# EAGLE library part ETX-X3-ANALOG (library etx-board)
VGA, LCD, Video, COM1, COM2, LPT/Floppy, IrDA, Mouse, Keyboard PARALLEL INTERFACE PINOUT, FLOPPY SUPPORT MODE PINOUT ETX Board Connector 100 Pos. Source: www.kontron.com/techlib/whitepapers/etx_spec.pdf
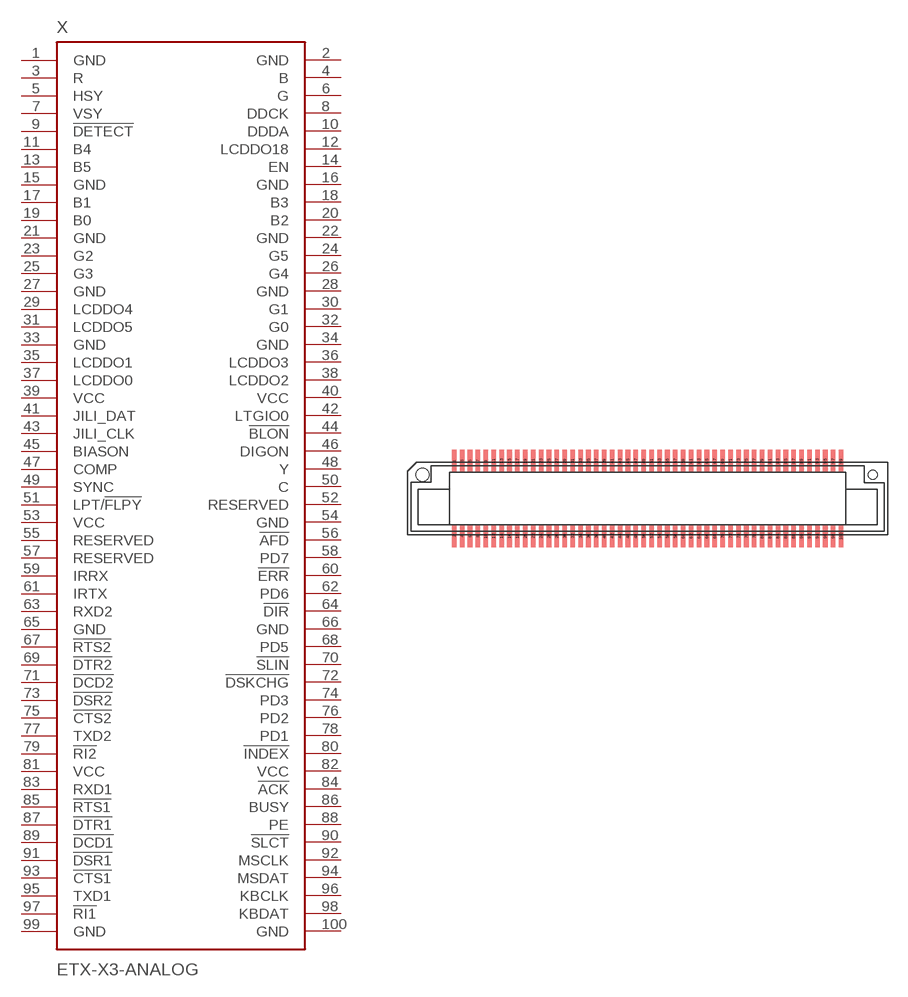
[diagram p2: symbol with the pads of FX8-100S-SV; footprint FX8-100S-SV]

Designator prefix X

## ETX-X3-ANALOG  [FX8-100S-SV]
1  GND  pwr
2  GND  pwr
3  R
4  B
5  HSY
6  G
7  VSY
8  DDCK
9  !DETECT
10  DDDA
11  B4
12  LCDDO18
13  B5
14  EN
15  GND  pwr
16  GND  pwr
17  B1
18  B3
19  B0
20  B2
21  GND  pwr
22  GND  pwr
23  G2
24  G5
25  G3
26  G4
27  GND  pwr
28  GND  pwr
29  LCDDO4
30  G1
31  LCDDO5
32  G0
33  GND  pwr
34  GND  pwr
35  LCDDO1
36  LCDDO3
37  LCDDO0
38  LCDDO2
39  VCC  pwr
40  VCC  pwr
41  JILI_DAT
42  LTGIO0
43  JILI_CLK
44  !BLON
45  BIASON
46  DIGON
47  COMP
48  Y
49  SYNC
50  C
51  LPT/!FLPY
52  RESERVED
53  VCC  pwr
54  GND  pwr
55  RESERVED
56  !AFD
57  RESERVED
58  PD7
59  IRRX
60  !ERR
61  IRTX
62  PD6
63  RXD2
64  !DIR
65  GND  pwr
66  GND  pwr
67  !RTS2
68  PD5
69  !DTR2
70  !SLIN
71  !DCD2
72  !DSKCHG
73  !DSR2
74  PD3
75  !CTS2
76  PD2
77  TXD2
78  PD1
79  !RI2
80  !INDEX
81  VCC  pwr
82  VCC  pwr
83  RXD1
84  !ACK
85  !RTS1
86  BUSY
87  !DTR1
88  PE
89  !DCD1
90  !SLCT
91  !DSR1
92  MSCLK
93  !CTS1
94  MSDAT
95  TXD1
96  KBCLK
97  !RI1
98  KBDAT
99  GND  pwr
100  GND  pwr

## Footprint FX8-100S-SV (pad centres in mm)
HIROSE - ETX Board Connector 100 Pos. Source: www.hirose.co.jp/cataloge_hp/e57800016.pdf www.kontron.com/techlib/whitepapers/etx_spec.pdf
smd 0.35 x 1.7: 1 -14.7,2.85; 2 -14.7,-2.85; 3 -14.1,2.85; 4 -14.1,-2.85; 5 -13.5,2.85; 6 -13.5,-2.85; 7 -12.9,2.85; 8 -12.9,-2.85; 9 -12.3,2.85; 10 -12.3,-2.85; 11 -11.7,2.85; 12 -11.7,-2.85; 13 -11.1,2.85; 14 -11.1,-2.85; 15 -10.5,2.85; 16 -10.5,-2.85; 17 -9.9,2.85; 18 -9.9,-2.85; 19 -9.3,2.85; 20 -9.3,-2.85; 21 -8.7,2.85; 22 -8.7,-2.85; 23 -8.1,2.85; 24 -8.1,-2.85; 25 -7.5,2.85; 26 -7.5,-2.85; 27 -6.9,2.85; 28 -6.9,-2.85; 29 -6.3,2.85; 30 -6.3,-2.85; 31 -5.7,2.85; 32 -5.7,-2.85; 33 -5.1,2.85; 34 -5.1,-2.85; 35 -4.5,2.85; 36 -4.5,-2.85; 37 -3.9,2.85; 38 -3.9,-2.85; 39 -3.3,2.85; 40 -3.3,-2.85; 41 -2.7,2.85; 42 -2.7,-2.85; 43 -2.1,2.85; 44 -2.1,-2.85; 45 -1.5,2.85; 46 -1.5,-2.85; 47 -0.9,2.85; 48 -0.9,-2.85; 49 -0.3,2.85; 50 -0.3,-2.85; 51 0.3,2.85; 52 0.3,-2.85; 53 0.9,2.85; 54 0.9,-2.85; 55 1.5,2.85; 56 1.5,-2.85; 57 2.1,2.85; 58 2.1,-2.85; 59 2.7,2.85; 60 2.7,-2.85; 61 3.3,2.85; 62 3.3,-2.85; 63 3.9,2.85; 64 3.9,-2.85; 65 4.5,2.85; 66 4.5,-2.85; 67 5.1,2.85; 68 5.1,-2.85; 69 5.7,2.85; 70 5.7,-2.85; 71 6.3,2.85; 72 6.3,-2.85; 73 6.9,2.85; 74 6.9,-2.85; 75 7.5,2.85; 76 7.5,-2.85; 77 8.1,2.85; 78 8.1,-2.85; 79 8.7,2.85; 80 8.7,-2.85; 81 9.3,2.85; 82 9.3,-2.85; 83 9.9,2.85; 84 9.9,-2.85; 85 10.5,2.85; 86 10.5,-2.85; 87 11.1,2.85; 88 11.1,-2.85; 89 11.7,2.85; 90 11.7,-2.85; 91 12.3,2.85; 92 12.3,-2.85; 93 12.9,2.85; 94 12.9,-2.85; 95 13.5,2.85; 96 13.5,-2.85; 97 14.1,2.85; 98 14.1,-2.85; 99 14.7,2.85; 100 14.7,-2.85
hole 1 at -17.1,1.8
hole 0.7 at 17.1,1.8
